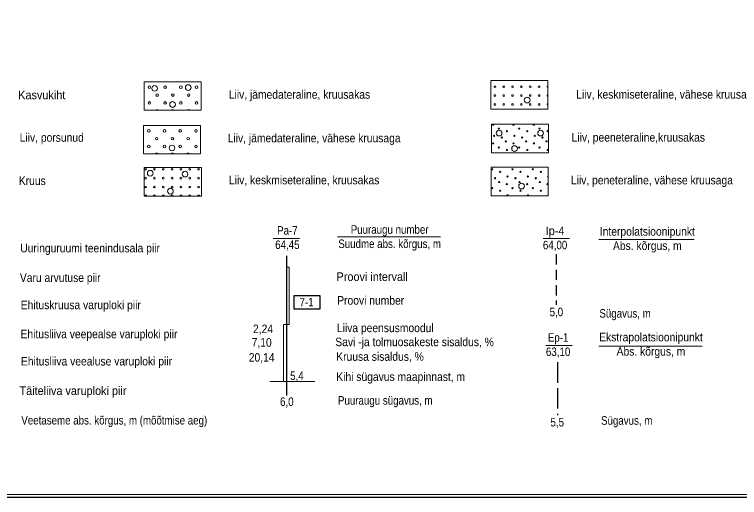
# Model space of a CAD drawing. Extents: x 640121 to 640955, y 6441885 to 6442246.
# Drawn here: x 640517.6 to 640771.8, y 6441889.4 to 6442058.6 of the extents above; entities that cross this region are included whole.
import ezdxf
from ezdxf.enums import TextEntityAlignment as Align

# ---------------------------------------------------------------- set-up
doc = ezdxf.new("R2010")
doc.units = 0
doc.header["$LTSCALE"] = 1.2
doc.linetypes.add('LONG_DASHED', pattern=[7.5, 6, -1.5])
doc.linetypes.add('MEDIUM_DASHED', pattern=[4.5, 3, -1.5])
doc.layers.add('50', color=7, linetype='Continuous', lineweight=13)

msp = doc.modelspace()

# ---------------------------------------------------------------- hatches: boundary and pattern name
at = {"layer": '50'}
for points in [[(640687.625, 6442018.621, 1), (640687.205, 6442018.621, 1)], [(640694.758, 6442018.621, 1), (640694.338, 6442018.621, 1)], [(640701.891, 6442018.621, 1), (640701.471, 6442018.621, 1)], [(640685.921, 6442016.087, 1), (640685.501, 6442016.087, 1)], [(640690.452, 6442017.712, 1), (640690.032, 6442017.712, 1)], [(640693.054, 6442016.087, 1), (640692.634, 6442016.087, 1)], [(640697.585, 6442017.712, 1), (640697.165, 6442017.712, 1)], [(640700.187, 6442016.087, 1), (640699.767, 6442016.087, 1)], [(640704.718, 6442017.712, 1), (640704.298, 6442017.712, 1)], [(640685.647, 6442013.443, 1), (640685.227, 6442013.443, 1)], [(640688.669, 6442015.481, 1), (640688.249, 6442015.481, 1)], [(640690.088, 6442014.159, 1), (640689.668, 6442014.159, 1)], [(640692.78, 6442013.443, 1), (640692.36, 6442013.443, 1)], [(640695.802, 6442015.481, 1), (640695.382, 6442015.481, 1)], [(640697.221, 6442014.159, 1), (640696.801, 6442014.159, 1)], [(640699.913, 6442013.443, 1), (640699.493, 6442013.443, 1)], [(640702.935, 6442015.481, 1), (640702.515, 6442015.481, 1)], [(640704.354, 6442014.159, 1), (640703.934, 6442014.159, 1)], [(640687.625, 6442012.025, 1), (640687.205, 6442012.025, 1)], [(640690.452, 6442011.116, 1), (640690.032, 6442011.116, 1)], [(640694.758, 6442012.025, 1), (640694.338, 6442012.025, 1)], [(640697.585, 6442011.116, 1), (640697.165, 6442011.116, 1)], [(640701.891, 6442012.025, 1), (640701.471, 6442012.025, 1)], [(640704.718, 6442011.116, 1), (640704.298, 6442011.116, 1)], [(640685.244, 6442004.369, 1), (640684.824, 6442004.369, 1)], [(640688.071, 6442003.461, 1), (640687.651, 6442003.461, 1)], [(640692.377, 6442004.369, 1), (640691.957, 6442004.369, 1)], [(640695.204, 6442003.461, 1), (640694.784, 6442003.461, 1)], [(640699.51, 6442004.369, 1), (640699.09, 6442004.369, 1)], [(640702.337, 6442003.461, 1), (640701.917, 6442003.461, 1)], [(640686.288, 6442001.23, 1), (640685.868, 6442001.23, 1)], [(640690.674, 6442001.836, 1), (640690.254, 6442001.836, 1)], [(640693.421, 6442001.23, 1), (640693.001, 6442001.23, 1)], [(640697.807, 6442001.836, 1), (640697.387, 6442001.836, 1)], [(640700.554, 6442001.23, 1), (640700.134, 6442001.23, 1)], [(640687.707, 6441999.908, 1), (640687.287, 6441999.908, 1)], [(640690.4, 6441999.192, 1), (640689.98, 6441999.192, 1)], [(640694.84, 6441999.908, 1), (640694.42, 6441999.908, 1)], [(640697.533, 6441999.192, 1), (640697.113, 6441999.192, 1)], [(640701.973, 6441999.908, 1), (640701.553, 6441999.908, 1)], [(640704.666, 6441999.192, 1), (640704.246, 6441999.192, 1)], [(640685.244, 6441997.773, 1), (640684.824, 6441997.773, 1)], [(640688.071, 6441996.865, 1), (640687.651, 6441996.865, 1)], [(640692.377, 6441997.773, 1), (640691.957, 6441997.773, 1)], [(640695.204, 6441996.865, 1), (640694.784, 6441996.865, 1)], [(640699.51, 6441997.773, 1), (640699.09, 6441997.773, 1)], [(640702.337, 6441996.865, 1), (640701.917, 6441996.865, 1)]]:
    msp.add_hatch(color=256, dxfattribs=at).paths.add_polyline_path(points)

# ---------------------------------------------------------------- linework, layer by layer
for p, q in [((640630.85, 6441980.69), (640666.92, 6441980.69)), ((640608.3, 6441980.17), (640617.52, 6441980.17)), ((640702.97, 6441980.17), (640712.19, 6441980.17)), ((640722.5, 6441979.8), (640755.9, 6441979.8)), ((640703.9, 6441942.64), (640713.12, 6441942.64)), ((640722.5, 6441942.43), (640758.65, 6441942.43)), ((640607.09, 6441930.04), (640622.89, 6441930.04))]:
    msp.add_line(p, q, dxfattribs=at)
at = {"layer": '50', "lineweight": 25}
msp.add_line((640612.89, 6441974.05), (640612.89, 6441925.15), dxfattribs=at)
at = {"layer": '50', "linetype": 'MEDIUM_DASHED', "lineweight": 25}
msp.add_line((640707.56, 6441974.59), (640707.56, 6441956.93), dxfattribs=at)
at = {"layer": '50', "linetype": 'LONG_DASHED', "lineweight": 25}
msp.add_line((640707.92, 6441936.75), (640707.92, 6441918.23), dxfattribs=at)
at = {"layer": '50', "lineweight": 25}
for points in [[(640121.33, 6442246.16), (640955.23, 6442246.16), (640955.23, 6441889.4), (640121.33, 6441889.4)], [(640615.68, 6441960.13), (640624.6, 6441960.13), (640624.6, 6441955.35), (640615.68, 6441955.35)]]:
    msp.add_lwpolyline(points, close=True, dxfattribs=at)
at = {"layer": '50'}
for points in [[(640122.33, 6442245.16), (640954.23, 6442245.16), (640954.23, 6441890.4), (640122.33, 6441890.4)], [(640563.02, 6442035.04), (640583.02, 6442035.04), (640583.02, 6442025.04), (640563.02, 6442025.04)], [(640684.59, 6442035.43), (640704.59, 6442035.43), (640704.59, 6442025.43), (640684.59, 6442025.43)], [(640562.83, 6442019.77), (640582.83, 6442019.77), (640582.83, 6442009.77), (640562.83, 6442009.77)], [(640684.79, 6442020.14), (640704.79, 6442020.14), (640704.79, 6442010.14), (640684.79, 6442010.14)], [(640563.09, 6442004.99), (640583.09, 6442004.99), (640583.09, 6441994.99), (640563.09, 6441994.99)], [(640684.72, 6442005.07), (640704.72, 6442005.07), (640704.72, 6441995.07), (640684.72, 6441995.07)], [(640613.89, 6441950.05), (640613.89, 6441970.05), (640612.89, 6441970.05), (640612.89, 6441950.05)], [(640611.89, 6441950.05), (640611.89, 6441930.05), (640612.89, 6441930.05), (640612.89, 6441950.05)]]:
    msp.add_lwpolyline(points, close=True, dxfattribs=at)
for centre, radius in [((640578.503, 6442033.01), 1), ((640564.848, 6442033.137), 0.45), ((640566.703, 6442032.725), 1), ((640570.364, 6442033.137), 0.45), ((640575.879, 6442033.137), 0.45), ((640581.395, 6442033.137), 0.45), ((640686.012, 6442033.304), 0.3), ((640689.112, 6442033.304), 0.3), ((640692.212, 6442033.304), 0.3), ((640695.312, 6442033.304), 0.3), ((640698.412, 6442033.304), 0.3), ((640701.512, 6442033.304), 0.3), ((640567.606, 6442030.379), 0.45), ((640573.122, 6442030.379), 0.45), ((640578.637, 6442030.379), 0.45), ((640686.012, 6442030.204), 0.3), ((640689.112, 6442030.204), 0.3), ((640692.212, 6442030.204), 0.3), ((640695.312, 6442030.204), 0.3), ((640697.332, 6442028.608), 1), ((640698.412, 6442030.204), 0.3), ((640701.512, 6442030.204), 0.3), ((640564.848, 6442027.621), 0.45), ((640570.364, 6442027.621), 0.45), ((640572.984, 6442027.11), 1), ((640575.879, 6442027.621), 0.45), ((640581.395, 6442027.621), 0.45), ((640686.012, 6442027.104), 0.3), ((640689.112, 6442027.104), 0.3), ((640692.212, 6442027.104), 0.3), ((640695.312, 6442027.104), 0.3), ((640698.412, 6442027.104), 0.3), ((640701.512, 6442027.104), 0.3), ((640687.415, 6442018.621), 0.21), ((640694.548, 6442018.621), 0.21), ((640701.681, 6442018.621), 0.21), ((640564.657, 6442017.866), 0.45), ((640570.173, 6442017.866), 0.45), ((640575.688, 6442017.866), 0.45), ((640581.204, 6442017.866), 0.45), ((640685.711, 6442016.087), 0.21), ((640687.478, 6442017.037), 1), ((640690.242, 6442017.712), 0.21), ((640692.844, 6442016.087), 0.21), ((640697.375, 6442017.712), 0.21), ((640699.977, 6442016.087), 0.21), ((640702.038, 6442017.037), 1), ((640704.508, 6442017.712), 0.21), ((640567.415, 6442015.108), 0.45), ((640572.931, 6442015.108), 0.45), ((640578.446, 6442015.108), 0.45), ((640685.437, 6442013.443), 0.21), ((640688.459, 6442015.481), 0.21), ((640689.878, 6442014.159), 0.21), ((640692.57, 6442013.443), 0.21), ((640695.592, 6442015.481), 0.21), ((640697.011, 6442014.159), 0.21), ((640699.703, 6442013.443), 0.21), ((640702.725, 6442015.481), 0.21), ((640704.144, 6442014.159), 0.21), ((640564.657, 6442012.35), 0.45), ((640570.173, 6442012.35), 0.45), ((640572.793, 6442011.839), 1), ((640575.688, 6442012.35), 0.45), ((640581.204, 6442012.35), 0.45), ((640687.415, 6442012.025), 0.21), ((640690.242, 6442011.116), 0.21), ((640692.902, 6442011.613), 1), ((640694.548, 6442012.025), 0.21), ((640697.375, 6442011.116), 0.21), ((640701.681, 6442012.025), 0.21), ((640704.508, 6442011.116), 0.21), ((640563.516, 6442004.364), 0.3), ((640565.18, 6442002.989), 1), ((640566.616, 6442004.364), 0.3), ((640569.716, 6442004.364), 0.3), ((640572.816, 6442004.364), 0.3), ((640575.916, 6442004.364), 0.3), ((640577.361, 6442002.704), 1), ((640579.016, 6442004.364), 0.3), ((640582.116, 6442004.364), 0.3), ((640685.034, 6442004.369), 0.21), ((640687.861, 6442003.461), 0.21), ((640692.167, 6442004.369), 0.21), ((640694.994, 6442003.461), 0.21), ((640699.3, 6442004.369), 0.21), ((640702.127, 6442003.461), 0.21), ((640563.516, 6442001.264), 0.3), ((640566.616, 6442001.264), 0.3), ((640569.716, 6442001.264), 0.3), ((640572.816, 6442001.264), 0.3), ((640575.916, 6442001.264), 0.3), ((640579.016, 6442001.264), 0.3), ((640582.116, 6442001.264), 0.3), ((640686.078, 6442001.23), 0.21), ((640690.464, 6442001.836), 0.21), ((640693.211, 6442001.23), 0.21), ((640697.597, 6442001.836), 0.21), ((640700.344, 6442001.23), 0.21), ((640563.516, 6441998.164), 0.3), ((640566.616, 6441998.164), 0.3), ((640569.716, 6441998.164), 0.3), ((640572.816, 6441998.164), 0.3), ((640575.916, 6441998.164), 0.3), ((640579.016, 6441998.164), 0.3), ((640582.116, 6441998.164), 0.3), ((640687.497, 6441999.908), 0.21), ((640690.19, 6441999.192), 0.21), ((640695.377, 6441998.48), 1), ((640694.63, 6441999.908), 0.21), ((640697.323, 6441999.192), 0.21), ((640701.763, 6441999.908), 0.21), ((640704.456, 6441999.192), 0.21), ((640572.223, 6441996.708), 1), ((640685.034, 6441997.773), 0.21), ((640687.861, 6441996.865), 0.21), ((640692.167, 6441997.773), 0.21), ((640694.994, 6441996.865), 0.21), ((640699.3, 6441997.773), 0.21), ((640702.127, 6441996.865), 0.21)]:
    msp.add_circle(centre, radius, dxfattribs=at)
for centre, radius, start, end in [((640704.612, 6442033.304), 0.3, 94.60819, 265.39181), ((640704.612, 6442030.204), 0.3, 94.60819, 265.39181), ((640704.612, 6442027.104), 0.3, 94.60819, 265.39181), ((640567.606, 6442024.864), 0.45, 23.21772, 156.78228), ((640573.122, 6442024.864), 0.45, 23.21772, 156.78228), ((640578.637, 6442024.864), 0.45, 23.21772, 156.78228), ((640685.437, 6442020.039), 0.21, 150.74597, 29.25403), ((640692.57, 6442020.039), 0.21, 150.74597, 29.25403), ((640699.703, 6442020.039), 0.21, 150.74597, 29.25403), ((640567.415, 6442009.592), 0.45, 23.21772, 156.78228), ((640572.931, 6442009.592), 0.45, 23.21772, 156.78228), ((640578.446, 6442009.592), 0.45, 23.21772, 156.78228), ((640704.73, 6442001.836), 0.21, 91.76464, 268.23536), ((640563.516, 6441995.064), 0.3, 345.47373, 194.52627), ((640566.616, 6441995.064), 0.3, 345.47373, 194.52627), ((640569.716, 6441995.064), 0.3, 345.47373, 194.52627), ((640572.816, 6441995.064), 0.3, 345.47373, 194.52627), ((640575.916, 6441995.064), 0.3, 345.47373, 194.52627), ((640579.016, 6441995.064), 0.3, 345.47373, 194.52627), ((640582.116, 6441995.064), 0.3, 345.47373, 194.52627), ((640690.464, 6441995.24), 0.21, 306.48162, 233.51838), ((640697.597, 6441995.24), 0.21, 306.48162, 233.51838), ((640704.73, 6441995.24), 0.21, 91.76464, 233.51838)]:
    msp.add_arc(centre, radius, start, end, dxfattribs=at)

# ---------------------------------------------------------------- texts
for s, width, p in [('Kasvukiht', 0.95, (640527.13, 6442028.91)), ('Liiv, jämedateraline, kruusakas', 0.9, (640617.5, 6442029.09)), ('Liiv, keskmiseteraline, vähese kruusaga', 0.9, (640746.445, 6442029.13)), ('Liiv, porsunud', 0.9, (640530.625, 6442014.02)), ('Liiv, jämedateraline, vähese kruusaga', 0.9, (640622.635, 6442013.82)), ('Liiv, peeneteraline,kruusakas', 0.9, (640736.31, 6442014.07)), ('Kruus', 0.9, (640523.805, 6441998.87)), ('Liiv, keskmiseteraline, kruusakas', 0.9, (640619.135, 6441999.11)), ('Liiv, peneteraline, vähese kruusaga', 0.9, (640741.08, 6441999.08)), ('Pa-7', 0.85, (640613.25, 6441981.46)), ('Puuraugu number', 0.85, (640649.11, 6441981.78)), ('Ip-4', 0.95, (640707.135, 6441981.33)), ('Interpolatsioonipunkt', 0.9, (640739.485, 6441981.11)), ('Uuringuruumi teenindusala piir', 0.9, (640544.075, 6441975.27)), ('64,45', 0.85, (640613.245, 6441976.46)), ('Suudme abs. kõrgus, m', 0.85, (640649.105, 6441976.78)), ('64,00', 0.85, (640707.13, 6441976.33)), ('Abs. kõrgus, m', 0.9, (640739.48, 6441976.11)), ('Varu arvutuse piir', 0.9, (640533.6, 6441964.91)), ('Proovi intervall', 0.95, (640642.995, 6441965.25)), ('Ehituskruusa varuploki piir', 0.9, (640540.805, 6441955.36)), ('7-1', 0.85, (640619.985, 6441956.34)), ('Proovi number', 0.9, (640642.48, 6441956.95)), ('5,0', 0.85, (640707.58, 6441952.89)), ('Sügavus, m', 0.85, (640731.67, 6441952.4)), ('Liiva peensusmoodul', 0.9, (640647.575, 6441947.32)), ('Ehitusliiva veepealse varuploki piir', 0.9, (640547.18, 6441945.18)), ('2,24', 0.9, (640604.72, 6441946.97)), ('7,10', 0.9, (640604.24, 6441942.22)), ('Savi -ja tolmuosakeste sisaldus, %', 0.9, (640657.86, 6441942.4)), ('Ep-1', 0.85, (640708.19, 6441943.95)), ('Ekstrapolatsioonipunkt', 0.9, (640740.75, 6441944.09)), ('20,14', 0.9, (640604.235, 6441936.98)), ('Kruusa sisaldus, %', 0.9, (640645.75, 6441937.28)), ('63,10', 0.85, (640708.195, 6441938.95)), ('Abs. kõrgus, m', 0.9, (640740.75, 6441939.09)), ('Ehitusliiva veealuse varuploki piir', 0.9, (640546.31, 6441935.64)), ('5,4', 0.85, (640616.59, 6441930.54)), ('Kihi sügavus maapinnast, m', 0.9, (640652.98, 6441930.21)), ('Täiteliiva varuploki piir', 0.95, (640538.075, 6441925.3)), ('Puuraugu sügavus, m', 0.85, (640647.58, 6441921.91)), ('6,0', 0.85, (640613.06, 6441921.48)), ('Veetaseme abs. kõrgus, m (mõõtmise aeg)', 0.85, (640552.555, 6441914.96)), ('5,5', 0.85, (640707.89, 6441914.28)), ('Sügavus, m', 0.85, (640732.245, 6441914.88))]:
    msp.add_text(s, height=3, dxfattribs=dict(at, width=width)).set_placement(p, align=Align.CENTER)

doc.saveas('drawing.dxf')
